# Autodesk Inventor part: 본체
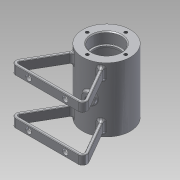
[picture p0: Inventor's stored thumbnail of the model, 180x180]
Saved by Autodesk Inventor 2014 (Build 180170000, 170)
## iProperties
Created: 2016-03
Part Number: 본체
Material: Aluminum 6061
Document SubType Name: Modeling
Designer: user
Mass: 212.886 g
Surface Area: 334.508 cm^2
Volume: 78.5558 cm^3
Density: 2.71 g/cm^3
Appearance: Aluminum - Flat
Author: user
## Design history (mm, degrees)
sketch "Sketch1"
  geometry: C1 r 26 at (0, 0); 1 further point
  constraints: 1 centre point, 1 coincident
  dimensions: "d0" = 52 diameter of C1
extrude "Extrusion1" new body sketch "Sketch1" stored distance "d1" = 70; taper "d2" = 0 deg
sketch "Sketch2"
  geometry: C1 r 26 at (0, 0) reference; C2 r 16 at (0, 0)
  constraints: 1 centre point, 1 coincident
  dimensions: "d3" = 32 diameter of C2
extrude "Extrusion2" cut sketch "Sketch2" distance "d4" = 12; taper "d5" = 0 deg
sketch "Sketch3"
  geometry: C1 r 16 at (0, 0) reference; C2 r 14 at (0, 0)
  constraints: 1 centre point, 1 coincident
  dimensions: "d6" = 28 diameter of C2
extrude "Extrusion3" cut sketch "Sketch3" distance "d7" = 2; taper "d8" = 0 deg
sketch "Sketch4"
  geometry: C1 r 26 at (0, 0) reference; C2 r 16 at (0, 0)
  constraints: 1 centre point, 1 coincident
  dimensions: "d9" = 32 diameter of C2
extrude "Extrusion4" cut sketch "Sketch4" distance "d10" = 12; taper "d11" = 0 deg
sketch "Sketch5"
  geometry: C1 r 16 at (0, 0) reference; C2 r 14 at (0, 0)
  constraints: 1 centre point, 1 coincident
  dimensions: "d12" = 28 diameter of C2
extrude "Extrusion5" cut sketch "Sketch5" distance "d13" = 2; taper "d14" = 0 deg
sketch "Sketch6"
  geometry: C1 r 14 at (0, 0) reference; C2 r 21 at (0, 0)
  constraints: 1 centre point, 1 coincident
  dimensions: "d15" = 42 diameter of C2
extrude "Extrusion6" cut sketch "Sketch6" distance "d16" = 42; taper "d17" = 0 deg
fillet "Fillet1" dims "d18" = 0.3
sketch "Sketch7"
  geometry: L1 (0, 0)-(0, 21); C1 r 26 at (0, 0) reference; 1 further point
  constraints: 2 end point, 1 coincident
  dimensions: "d19" = 21 distance of L1.start L1.end
hole "Hole1" sketch "Sketch7" at (0, 21) diameter "d20" = 3.459; stored, may be unused: countersink angle "d24" = 90 deg, drill point angle "d26" = 118 deg; dims "d21" = 8, "d22" = 4, "d23" = 2, "d25" = 10
pattern_circular "Circular Pattern1" dims angle "d28" = 360 deg
mirror "Mirror1"
workplane "Work Plane1"
sketch "Sketch8"
  geometry: C1 r 5 at (0, 0); 1 further point
  constraints: 1 centre point, 1 coincident
extrude "Extrusion7" join sketch "Sketch8" stored distance "d31" = 42; taper "d32" = 0 deg
sketch "Sketch9"
  geometry: C1 r 5 at (0, 0) reference; 1 further point
  constraints: 1 coincident
hole "Hole2" sketch "Sketch9" at (0, 0) diameter "d33" = 5.188; stored, may be unused: countersink angle "d37" = 90 deg, drill point angle "d39" = 118 deg; dims "d34" = 10, "d35" = 4, "d36" = 2, "d38" = 10
sketch "Sketch10"
  geometry: L1 (0, 0)-(0, -10); L2 (0, 0)-(7.506, -28.012); C1 r 26 at (0, 0) reference; 1 further point
  constraints: 4 end point, 1 coincident
  dimensions: "d41" = 10 distance of L1.start L1.end; "d45" = 15 deg angle of L2 L1
workplane "Work Plane2"
sketch "Sketch11"
  geometry: C1 r 6 at (0, 0); 1 further point
  constraints: 1 centre point, 1 coincident
extrude "Extrusion8" join sketch "Sketch11" stored distance "d46" = 42; taper "d47" = 0 deg
sketch "Sketch12"
  geometry: C1 r 6 at (0, 0) reference; 1 further point
  constraints: 1 coincident
hole "Hole3" sketch "Sketch12" at (0, 0) diameter "d48" = 5.188; stored, may be unused: countersink angle "d52" = 90 deg, drill point angle "d54" = 118 deg; dims "d49" = 10, "d50" = 4, "d51" = 2, "d53" = 10
fillet "Fillet2" dims "d55" = 2
chamfer "Chamfer1" distance "d56" = 1; stored, may be unused: second distance "d57" = 2, angle "d58" = 45 deg
fillet "Fillet3" dims "d59" = 3
workplane "Work Plane3"
sketch "Sketch13"
  geometry: L1 (-3.002, -20.739)-(-3.002, 20.739); L2 (-3.002, 20.739)-(3.002, 20.739); L3 (3.002, 20.739)-(3.002, -20.739); L4 (3.002, -20.739)-(-3.002, -20.739); 1 further point
  constraints: 2 other
emboss "Emboss1" sketch "Sketch13" dims "d61" = 0.5, "d62" = 0
workplane "Work Plane4"
sketch "Sketch14"
  geometry: L1 (-33.934, -65)-(33.934, -65); L2 (16.613, -20)-(38.264, -57.5); L3 (-16.613, -20)-(-38.264, -57.5); L4 (0, 0)-(0, -10) reference; L5 (14.183, -21.791)-(35.666, -59); L6 (33.934, -62)-(-33.934, -62); L7 (-35.666, -59)-(-14.183, -21.791); A1 r 26 centre (0, 0) between (-16.613, -20) and (16.613, -20) reference; A2 r 5 centre (-33.934, -60) between (-38.264, -57.5) and (-33.934, -65); A3 r 5 centre (33.934, -60) between (33.934, -65) and (38.264, -57.5); A4 r 2 centre (33.934, -60) between (33.934, -62) and (35.666, -59); A5 r 2 centre (-33.934, -60) between (-35.666, -59) and (-33.934, -62); A6 r 26 centre (0, 0) between (-16.613, -20) and (-14.198, -21.781); A7 r 26 centre (0, 0) between (14.198, -21.781) and (16.613, -20); 1 further point
  constraints: 16 point on circle, 14 end point, 6 centre point, 4 tangent, 2 coincident, 1 equal radius, 1 horizontal, 1 vertical, 2 other
  dimensions: "d64" = 65 distance from line of L1 point (0, 0); "d67" = 60 deg angle of L2 L3; "d68" = 10 distance of L4.start L4.end; "d70" = 30 deg angle of L3 L4; "d71" = 5 radius of A2; "d88" = 4.38749 distance from line of point (0, 0) L2; "d89" = 4.38749 distance from line of point (0, 0) L3; "d90" = 3 distance between parallel lines of L1 L6; "d91" = 3 distance between parallel lines of L3 L7; "d92" = 3 distance between parallel lines of L2 L5
extrude "Extrusion9" join sketch "Sketch14" distance "d93" = 10; taper "d94" = 0 deg
sketch "Sketch15"
  geometry: L1 (33.934, -20)-(33.934, 5) reference; L2 (33.934, 5)-(53.934, 5); L3 (33.934, 5)-(13.934, 5); 2 further points
  constraints: 6 end point, 2 coincident, 2 perpendicular, 1 vertical
  dimensions: "d99" = 25 distance from line of L1.start L2; "d100" = 20 distance of L1.end L2.end; "d101" = 40 distance of L2.end L3.end
hole "Hole4" sketch "Sketch15" at (13.934, 5), (53.934, 5) diameter "d102" = 6; stored, may be unused: countersink angle "d106" = 90 deg, drill point angle "d108" = 118 deg; dims "d103" = 10, "d104" = 4, "d105" = 2, "d107" = 10
fillet "Fillet4" dims "d109" = 0.5
mirror "Mirror2"
fillet "Fillet5" dims "d110" = 3
body "Solid1"
other parameters: "d30" = 29, "d60" = -26
